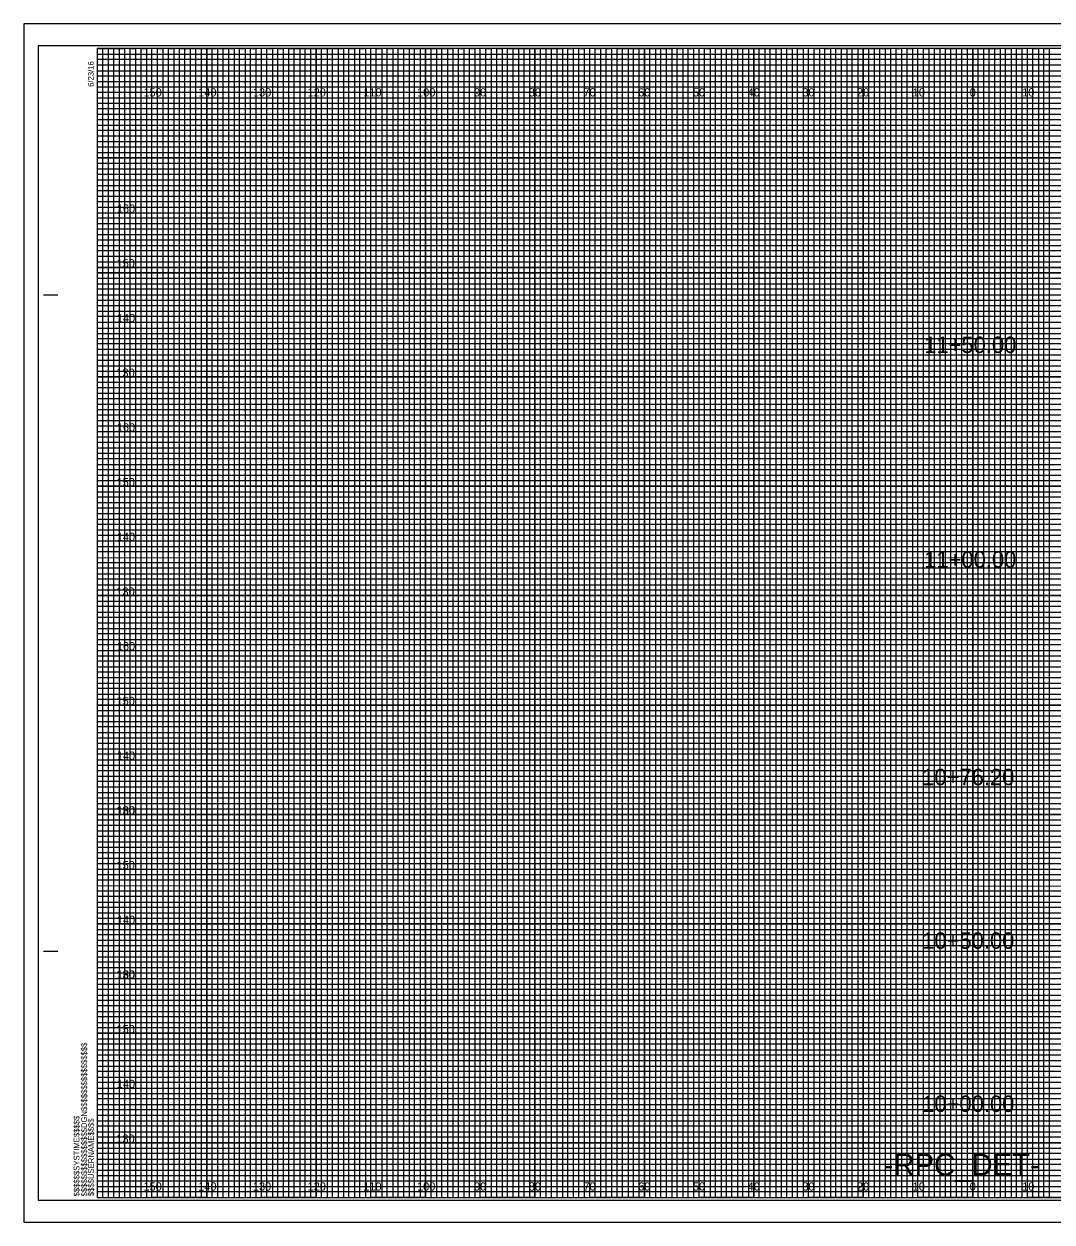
# Model space of a CAD drawing. Extents: x -13 to 323, y -5 to 654.
# Drawn here: x -13.4 to 174.5, y -4.5 to 214.5 of the extents above; entities that cross this region are included whole.
import ezdxf

# ---------------------------------------------------------------- set-up
doc = ezdxf.new("R2010")
doc.units = 0
for name, color, linetype in [('Exist Cross Section Cell', 7, 'Continuous'), ('Exist XS Center Line Elevation Label', 7, 'Continuous'), ('Exist XS Ground Line', 7, 'Continuous'), ('Prop CMT Pvmt Course 1', 7, 'Continuous'), ('Prop CMT Pvmt Course 2', 7, 'Continuous'), ('Prop CMT Pvmt Course 3', 7, 'Continuous'), ('Prop CMT Pvmt Surface', 7, 'Continuous'), ('Prop CMT Pvmt Surface Shoulder', 7, 'Continuous'), ('Prop CMT Shld Paved Course 1', 7, 'Continuous'), ('Prop CMT Shld Paved Course 2', 7, 'Continuous'), ('Prop CMT Shld Paved Course 3', 7, 'Continuous'), ('Prop CMT Slope Grass', 7, 'Continuous'), ('Prop XS Earthwork Shape', 7, 'Continuous')]:
    doc.layers.add(name, color=color, linetype=linetype)

msp = doc.modelspace()

# ---------------------------------------------------------------- linework, layer by layer
at = {"layer": 'Exist XS Center Line Elevation Label'}
for points in [[(0, 210), (5, 210), (5, 0), (15, 0), (15, 210), (25, 210), (25, 0), (35, 0), (35, 210), (45, 210), (45, 0), (55, 0), (55, 210), (65, 210), (65, 0), (75, 0), (75, 210), (85, 210), (85, 0), (95, 0), (95, 210), (105, 210), (105, 0), (115, 0), (115, 210), (125, 210), (125, 0), (135, 0), (135, 210), (145, 210), (145, 0), (155, 0), (155, 210), (165, 210), (165, 0), (175, 0)], [(0, 205), (275, 205)], [(0, 185), (320, 185), (320, 195), (0, 195)], [(0, 165), (320, 165), (320, 175), (0, 175)], [(0, 145), (320, 145), (320, 155), (0, 155)], [(0, 125), (320, 125), (320, 135), (0, 135)], [(0, 105), (320, 105), (320, 115), (0, 115)], [(0, 85), (320, 85), (320, 95), (0, 95)], [(0, 65), (320, 65), (320, 75), (0, 75)], [(0, 45), (320, 45), (320, 55), (0, 55)], [(0, 25), (320, 25), (320, 35), (0, 35)], [(0, 5), (320, 5), (320, 15), (0, 15)]]:
    msp.add_lwpolyline(points, dxfattribs=at)
at = {"layer": 'Exist XS Ground Line'}
for p, q in [((10, 210), (0, 210)), ((10, 0), (10, 210)), ((30, 210), (20, 210)), ((20, 210), (20, 0)), ((30, 0), (30, 210)), ((50, 210), (40, 210)), ((40, 210), (40, 0)), ((50, 0), (50, 210)), ((70, 210), (60, 210)), ((60, 210), (60, 0)), ((70, 0), (70, 210)), ((90, 210), (80, 210)), ((80, 210), (80, 0)), ((90, 0), (90, 210)), ((110, 210), (100, 210)), ((100, 210), (100, 0)), ((110, 0), (110, 210)), ((130, 210), (120, 210)), ((120, 210), (120, 0)), ((130, 0), (130, 210)), ((150, 210), (140, 210)), ((140, 210), (140, 0)), ((150, 0), (150, 210)), ((170, 210), (160, 210)), ((160, 210), (160, 0)), ((170, 0), (170, 210)), ((20, 0), (10, 0)), ((40, 0), (30, 0)), ((60, 0), (50, 0)), ((80, 0), (70, 0)), ((100, 0), (90, 0)), ((120, 0), (110, 0)), ((140, 0), (130, 0)), ((160, 0), (150, 0)), ((180, 0), (170, 0))]:
    msp.add_line(p, q, dxfattribs=at)
for points in [[(0, 200), (320, 200), (320, 190), (0, 190)], [(0, 180), (320, 180), (320, 170), (0, 170)], [(0, 160), (320, 160), (320, 150), (0, 150)], [(0, 140), (320, 140), (320, 130), (0, 130)], [(0, 120), (320, 120), (320, 110), (0, 110)], [(0, 100), (320, 100), (320, 90), (0, 90)], [(0, 80), (320, 80), (320, 70), (0, 70)], [(0, 60), (320, 60), (320, 50), (0, 50)], [(0, 40), (320, 40), (320, 30), (0, 30)], [(0, 20), (320, 20), (320, 10), (0, 10)]]:
    msp.add_lwpolyline(points, dxfattribs=at)
at = {"layer": 'Prop CMT Pvmt Course 1'}
for p, q in [((0, 209), (260, 209)), ((260, 207.98), (0, 207.98)), ((0, 207.98), (0, 207)), ((0, 207), (260, 207)), ((260, 205.89), (0, 205.89)), ((0, 205.89), (0, 204)), ((0, 204), (320, 204))]:
    msp.add_line(p, q, dxfattribs=at)
for points in [[(0, 203), (270, 203), (320, 203), (320, 202), (0, 202)], [(0, 201), (320, 201), (320, 199), (0, 199)], [(0, 198), (320, 198), (320, 197), (0, 196.98)], [(0, 196), (320, 196), (320, 194), (0, 194)], [(0, 193), (320, 193), (320, 192), (0, 192)], [(0, 191), (320, 191), (320, 189), (0, 189)], [(0, 188), (320, 188), (320, 187), (0, 187)], [(0, 186), (320, 186), (320, 184), (0, 184)], [(0, 183), (320, 183), (320, 182), (0, 182)], [(0, 181), (320, 181), (320, 179), (0, 179)], [(0, 178), (320, 178), (320, 177), (0, 177)], [(0, 176), (320, 176), (320, 173.95), (320, 173), (320, 172), (0, 172)], [(0, 174), (320, 174), (320, 173), (0, 173)], [(0, 171), (320, 171), (320, 169), (0, 169.03)], [(0, 169.03), (320, 169), (320, 168), (0, 168)], [(0, 167), (320, 167), (320, 166), (0, 166)], [(0, 164), (320, 164), (320, 163), (0, 163)], [(0, 162), (320, 162), (320, 161), (0, 161)], [(-0.07, 158.89), (320, 158.89), (320, 157.88), (-0.07, 157.88)], [(0, 157), (320, 157), (320, 156), (0, 156)], [(0, 154), (320, 154), (320, 153), (0, 153)], [(0, 152), (320, 152), (320, 151), (0, 151)], [(0, 149), (320, 149), (320, 148), (0, 148)], [(0, 147), (320, 147), (320, 146), (0, 146)], [(0, 144), (320, 144), (320, 143), (0, 143)], [(0, 142), (320, 142), (320, 141), (0, 141)], [(0, 139), (320, 139), (319.99, 137.98), (0, 138)], [(0, 137), (320, 137), (320, 136), (0, 136)], [(0, 134), (320, 134), (320, 133), (0, 133)], [(0, 132), (320, 132), (320, 131), (0, 131)], [(0, 129), (320, 129), (320, 128), (0, 128)], [(0, 127), (320, 127), (320, 126), (0, 126)], [(0, 124), (320, 124), (320, 123), (0, 123)], [(0, 122), (320, 122), (320, 121), (0, 121)], [(0, 119), (320, 119), (320, 118), (0, 118)], [(0, 116.99), (320.07, 116.91), (320, 116), (0, 116)], [(0, 114), (320, 114), (320, 113), (0, 113)], [(0, 112), (320, 112), (320, 111), (0, 111)], [(0, 109), (320, 109), (320, 108), (0, 108)], [(0, 107), (320, 107), (320, 106), (0, 106)], [(0, 104), (320, 104), (320, 103), (0, 103)], [(0, 102), (320, 102), (320, 101), (0, 101)], [(0, 99), (320, 99), (320, 98), (0, 98)], [(0, 97), (320, 97), (320, 96), (0, 96)], [(0, 94), (320, 94), (320, 93), (0, 93)], [(0, 92), (320, 92), (320, 91), (0, 91)], [(0, 89), (320, 89), (320, 88), (0, 88)], [(0, 87), (320, 87), (320, 86), (0, 86)], [(0, 84), (320, 84), (320, 83), (0, 83)], [(0, 82), (320, 82), (320, 81), (0, 81)], [(0, 79), (320, 79), (319.99, 77.98), (0, 78)], [(0, 77), (320, 77), (320, 76), (0, 76)], [(0, 74), (320, 74), (320, 73), (0, 73)], [(0, 72), (320, 72), (320, 71), (0, 71)], [(0, 69), (320, 69), (320, 68), (0, 68)], [(0, 67), (320, 67), (320, 66), (0, 66)], [(0, 64), (320, 64), (320, 63), (0, 63)], [(0, 62), (320, 62), (320, 61), (0, 61)], [(0, 59), (320, 59), (320, 58), (0, 58)], [(0, 56.99), (320.07, 56.91), (320, 56), (0, 56)], [(0, 54), (320, 54), (320, 53), (0, 53)], [(0, 52), (320, 52), (320, 51), (0, 51)], [(0, 49), (320, 49), (320, 48), (0, 48)], [(0, 47), (320, 47), (320, 46), (0, 46)], [(0, 44), (320, 44), (320, 43), (0, 43)], [(0, 42), (320, 42), (320, 41), (0, 41)], [(0, 39), (320, 39), (320, 38), (0, 38)], [(0, 37), (320, 37), (320, 36), (0, 36)], [(0, 34), (320, 34), (320, 33), (0, 33)], [(0, 32), (320, 32), (320, 31), (0, 31)], [(0, 29), (320, 29), (320, 28), (0, 28)], [(0, 27), (320, 27), (320, 26), (0, 26)], [(0, 24), (320, 24), (320, 23), (0, 23)], [(0, 22), (320, 22), (320, 21), (0, 21)], [(0, 19), (320, 19), (320, 18), (0, 18)], [(0, 17), (320, 17), (320, 16), (0, 16)], [(0, 14), (320, 14), (320, 13), (0, 13)], [(0, 12), (320, 12), (320, 11), (0, 11)], [(0, 9), (320, 9), (320, 8), (0, 8)], [(0, 7), (320, 7), (320, 6), (0, 6)], [(0, 4), (320, 4), (320, 3), (0, 3)], [(0, 2), (320, 2), (320, 1), (0, 1)]]:
    msp.add_lwpolyline(points, dxfattribs=at)
at = {"layer": 'Prop CMT Pvmt Surface'}
for points in [[(0, 0), (1, 0), (1, 210), (2, 210), (2, 0)], [(2, 0), (3, 0), (3, 210), (4, 210), (4, 0)], [(5, 0), (6, 0), (6, 210), (7, 210), (7, 0)], [(7, 0), (8, 0), (8, 210), (9, 210), (9, 0)], [(10, 0), (11, 0), (11, 210), (12, 210), (12, 0)], [(12, 0), (13, 0), (13, 210), (14, 210), (14, 0)], [(15, 0), (16, 0), (16, 210), (17, 210), (17, 0)], [(17, 0), (18, 0), (18, 210), (19, 210), (19, 0)], [(20, 0), (21, 0), (21, 210), (22, 210), (22, 0)], [(22, 0), (23, 0), (23, 210), (24, 210), (24, 0)], [(25, 0), (26, 0), (26, 210), (27, 210), (27, 0)], [(27, 0), (28, 0), (28, 210), (29, 210), (29, 0)], [(30, 0), (31, 0), (31, 210), (32, 210), (32, 0)], [(32, 0), (33, 0), (33, 210), (34, 210), (34, 0)], [(35, 0), (36, 0), (36, 210), (37, 210), (37, 0)], [(37, 0), (38, 0), (38, 210), (39, 210), (39, 0)], [(40, 0), (41, 0), (41, 210), (42, 210), (42, 0)], [(42, 0), (43, 0), (43, 210), (44, 210), (44, 0)], [(45, 0), (46, 0), (46, 210), (47, 210), (47, 0)], [(47, 0), (48, 0), (48, 210), (49, 210), (49, 0)], [(50, 0), (51, 0), (51, 210), (52, 210), (52, 0)], [(52, 0), (53, 0), (53, 210), (54, 210), (54, 0)], [(55, 0), (56, 0), (56, 210), (57, 210), (57, 0)], [(57, 0), (58, 0), (58, 210), (59, 210), (59, 0)], [(60, 0), (61, 0), (61, 210), (62, 210), (62, 0)], [(62, 0), (63, 0), (63, 210), (64, 210), (64, 0)], [(65, 0), (66, 0), (66, 210), (67, 210), (67, 0)], [(67, 0), (68, 0), (68, 210), (69, 210), (69, 0)], [(70, 0), (71, 0), (71, 210), (72, 210), (72, 0)], [(72, 0), (73, 0), (73, 210), (74, 210), (74, 0)], [(75, 0), (76, 0), (76, 210), (77, 210), (77, 0)], [(77, 0), (78, 0), (78, 210), (79, 210), (79, 0)], [(80, 0), (81, 0), (81, 210), (82, 210), (82, 0)], [(82, 0), (83, 0), (83, 210), (84, 210), (84, 0)], [(85, 0), (86, 0), (86, 210), (87, 210), (87, 0)], [(87, 0), (88, 0), (88, 210), (89, 210), (89, 0)], [(90, 0), (91, 0), (91, 210), (92, 210), (92, 0)], [(92, 0), (93, 0), (93, 210), (94, 210), (94, 0)], [(95, 0), (96, 0), (96, 210), (97, 210), (97, 0)], [(97, 0), (98, 0), (98, 210), (99, 210), (99, 0)], [(100, 0), (101, 0), (101, 210), (102, 210), (102, 0)], [(102, 0), (103, 0), (103, 210), (104, 210), (104, 0)], [(105, 0), (106, 0), (106, 210), (107, 210), (107, 0)], [(107, 0), (108, 0), (108, 210), (109, 210), (109, 0)], [(110, 0), (111, 0), (111, 210), (112, 210), (112, 0)], [(112, 0), (113, 0), (113, 210), (114, 210), (114, 0)], [(115, 0), (116, 0), (116, 210), (117, 210), (117, 0)], [(117, 0), (118, 0), (118, 210), (119, 210), (119, 0)], [(120, 0), (121, 0), (121, 210), (122, 210), (122, 0)], [(122, 0), (123, 0), (123, 210), (124, 210), (124, 0)], [(125, 0), (126, 0), (126, 210), (127, 210), (127, 0)], [(127, 0), (128, 0), (128, 210), (129, 210), (129, 0)], [(130, 0), (131, 0), (131, 210), (132, 210), (132, 0)], [(132, 0), (133, 0), (133, 210), (134, 210), (134, 0)], [(135, 0), (136, 0), (136, 210), (137, 210), (137, 0)], [(137, 0), (138, 0), (138, 210), (139, 210), (139, 0)], [(140, 0), (141, 0), (141, 210), (142, 210), (142, 0)], [(142, 0), (143, 0), (143, 210), (144, 210), (144, 0)], [(145, 0), (146, 0), (146, 210), (147, 210), (147, 0)], [(147, 0), (148, 0), (148, 210), (149, 210), (149, 0)], [(150, 0), (151, 0), (151, 210), (152, 210), (152, 0)], [(152, 0), (153, 0), (153, 210), (154, 210), (154, 0)], [(155, 0), (156, 0), (156, 210), (157, 210), (157, 0)], [(157, 0), (158, 0), (158, 210), (159, 210), (159, 0)], [(160, 0), (161, 0), (161, 210), (162, 210), (162, 0)], [(162, 0), (163, 0), (163, 210), (164, 210), (164, 0)], [(165, 0), (166, 0), (166, 210), (167, 210), (167, 0)], [(167, 0), (168, 0), (168, 210), (169, 210), (169, 0)], [(170, 0), (171, 0), (171, 210), (172, 210), (172, 0)], [(172, 0), (173, 0), (173, 210), (174, 210), (174, 0)]]:
    msp.add_lwpolyline(points, dxfattribs=at)
at = {"layer": 'Prop CMT Shld Paved Course 1'}
msp.add_lwpolyline([(-10.8, -0.5), (322.4, -0.5), (322.4, 210.5), (-10.8, 210.5)], close=True, dxfattribs=at)
at = {"layer": 'Prop CMT Shld Paved Course 2'}
for p, q in [((10, 0), (10, 210)), ((20, 0), (20, 210)), ((30, 0), (30, 210)), ((40, 0), (40, 210)), ((50, 0), (50, 210)), ((60, 0), (60, 210)), ((70, 0), (70, 210)), ((80, 0), (80, 210)), ((90, 0), (90, 210)), ((100, 0), (100, 210)), ((110, 0), (110, 210)), ((120, 0), (120, 210)), ((130, 0), (130, 210)), ((140, 0), (140, 210)), ((150, 0), (150, 210)), ((160, 0), (160, 210)), ((170, 0), (170, 210)), ((0, 200), (320, 200)), ((0, 190), (320, 190)), ((0, 180), (320, 180)), ((0, 170), (320, 170)), ((0, 160), (320, 160)), ((0, 150), (320, 150)), ((0, 140), (320, 140)), ((0, 130), (320, 130)), ((0, 120), (320, 120)), ((0, 110), (320, 110)), ((0, 100), (320, 100)), ((0, 90), (320, 90)), ((0, 80), (320, 80)), ((0, 70), (320, 70)), ((0, 60), (320, 60)), ((0, 50), (320, 50)), ((0, 40), (320, 40)), ((0, 30), (320, 30)), ((0, 20), (320, 20)), ((0, 10), (320, 10))]:
    msp.add_line(p, q, dxfattribs=at)
at = {"layer": 'Prop CMT Shld Paved Course 3'}
for p, q in [((323.3, 214.5), (-13.4, 214.5)), ((-13.4, 214.5), (-13.4, -4.5)), ((-13.4, -4.5), (323.3, -4.5))]:
    msp.add_line(p, q, dxfattribs=at)
at = {"layer": 'Prop CMT Slope Grass'}
for p, q in [((-9.8, 165), (-7.3, 165)), ((-9.7, 165), (-7.2, 165)), ((-9.8, 45), (-7.3, 45)), ((-9.7, 45), (-7.2, 45)), ((0, 0), (0, 0)), ((0, 0), (0, 0)), ((0, 0), (0, 0)), ((0, 0), (0, 0)), ((0, 0), (0, 0)), ((0, 0), (0, 0)), ((0, 0), (0, 0))]:
    msp.add_line(p, q, dxfattribs=at)
msp.add_lwpolyline([(320, 210), (0, 210), (0, 0), (320, 0)], close=True, dxfattribs=at)
at = {"layer": 'Prop XS Earthwork Shape'}
msp.add_lwpolyline([(-13.4, -4.5), (323.3, -4.5), (323.3, 214.5), (-13.4, 214.5)], close=True, dxfattribs=at)

# ---------------------------------------------------------------- texts
at = {"layer": 'Exist Cross Section Cell'}
for s, p in [('150', (8.44, 201.25)), ('140', (18.44, 201.25)), ('130', (28.44, 201.25)), ('120', (38.44, 201.25)), ('110', (48.62, 201.25)), ('100', (58.44, 201.25)), ('90', (68.86, 201.25)), ('80', (78.86, 201.25)), ('70', (88.86, 201.25)), ('60', (98.86, 201.25)), ('50', (108.86, 201.25)), ('40', (118.86, 201.25)), ('30', (128.86, 201.25)), ('20', (138.86, 201.25)), ('10', (149.04, 201.25)), ('0', (159.45, 201.25)), ('0', (159.45, 201.25)), ('10', (169.04, 201.25)), ('150', (8.44, 1.25)), ('140', (18.44, 1.25)), ('130', (28.44, 1.25)), ('120', (38.44, 1.25)), ('110', (48.62, 1.25)), ('100', (58.44, 1.25)), ('90', (68.86, 1.25)), ('80', (78.86, 1.25)), ('70', (88.86, 1.25)), ('60', (98.86, 1.25)), ('50', (108.86, 1.25)), ('40', (118.86, 1.25)), ('30', (128.86, 1.25)), ('20', (138.86, 1.25)), ('10', (149.04, 1.25)), ('0', (159.45, 1.25)), ('0', (159.45, 1.25)), ('10', (169.04, 1.25))]:
    msp.add_text(s, height=1.5, dxfattribs=at).set_placement(p)
at = {"layer": 'Prop CMT Pvmt Course 2'}
for s, p in [('160', (3.57, 180)), ('150', (3.52, 170)), ('140', (3.57, 160)), ('130', (3.49, 150)), ('160', (3.57, 140)), ('150', (3.52, 130)), ('140', (3.57, 120)), ('130', (3.49, 110)), ('160', (3.57, 100)), ('150', (3.52, 90)), ('140', (3.57, 80)), ('130', (3.49, 70)), ('160', (3.57, 70)), ('150', (3.52, 60)), ('140', (3.57, 50)), ('130', (3.49, 40)), ('160', (3.57, 40)), ('150', (3.52, 30)), ('140', (3.57, 20)), ('130', (3.49, 10))]:
    msp.add_text(s, height=1.5, dxfattribs=at).set_placement(p)
at = {"layer": 'Prop CMT Pvmt Course 3'}
for s, p in [('11+50.00', (151.13, 154.35)), ('11+00.00', (151.13, 115.11)), ('10+76.20', (150.77, 75.35)), ('10+50.00', (150.77, 45.45)), ('10+00.00', (150.77, 15.62))]:
    msp.add_text(s, height=3, dxfattribs=at).set_placement(p)
at = {"layer": 'Prop CMT Pvmt Surface Shoulder'}
msp.add_text('-RPC_DET-', height=4, dxfattribs=at).set_placement((143.73, 4))
at = {"layer": 'Prop CMT Slope Grass'}
for s, p in [('6/23/16', (-0.65, 203)), ('$$$$$$$$$$$$$$$$DGN$$$$$$$$$$$$$$$$', (-1.88, 0.18)), ('$$$$$$SYSTIME$$$$$', (-3.26, 0.18)), ('$$$$USERNAME$$$$', (-0.62, 0.23))]:
    msp.add_text(s, height=1.05, rotation=90, dxfattribs=at).set_placement(p)

doc.saveas('drawing.dxf')
